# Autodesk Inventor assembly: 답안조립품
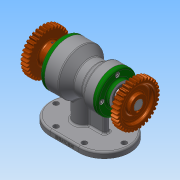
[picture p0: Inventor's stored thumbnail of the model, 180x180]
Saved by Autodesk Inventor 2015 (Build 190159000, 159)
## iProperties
Created: 2020-01
Part Number: 답안조립품
Document SubType Name: Assembly
Designer: user
Author: user
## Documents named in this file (13)
- C:\Users\user\Desktop\700104V1008\답안조립품.iam
- C:\Users\user\Desktop\700104V1008\1.본체.ipt
- C:\Users\user\Desktop\700104V1008\앞커버.ipt
- C:\Users\user\Desktop\700104V1008\뒤커버.ipt
- C:\Users\user\Desktop\700104V1008\베어링 6203.ipt
- C:\Users\user\Desktop\700104V1008\베어링 6205.ipt
- C:\Users\user\Desktop\700104V1008\축.ipt
- C:\Users\user\Desktop\700104V1008\오일 실 17 30 8.ipt
- C:\Users\user\Desktop\700104V1008\오일 실 25 38 8.ipt
- C:\Users\user\Desktop\700104V1008\키 5 x 5 x 18.ipt
- C:\Users\user\Desktop\700104V1008\스퍼기어.ipt
- C:\Users\user\Desktop\700104V1008\멈춤나사 M3.ipt
- C:\Users\user\Desktop\700104V1008\볼트 M4.ipt
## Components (1 placed, 1 different names)
1. 1.본체:1 — 각도:3, 각도:4
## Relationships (2: Angle 2)
- 각도:3 [Angle]: 1.본체:1
- 각도:4 [Angle]: 1.본체:1
